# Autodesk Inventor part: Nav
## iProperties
Created: 2010-02
Part Number: Nav
Document SubType Name: Modeling
Designer: a31883
Density: 1 g/cm^3
Author: a31883
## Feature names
1. Extrusion1
2. Extrusion2
3. Hole1
4. Circular Pattern1
